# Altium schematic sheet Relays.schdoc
size 144 x 146 mm
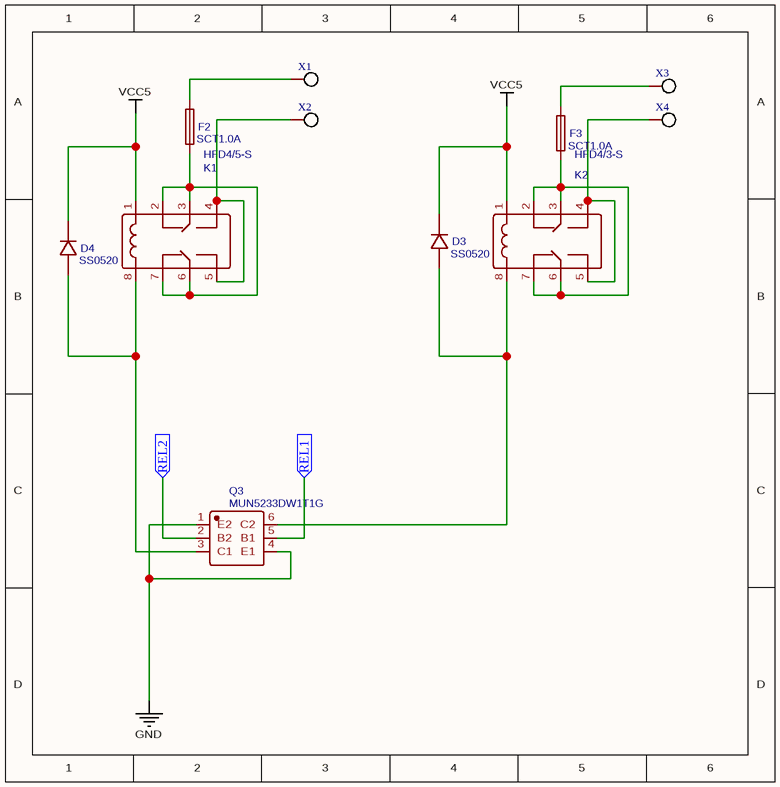
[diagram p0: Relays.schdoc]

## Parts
D3  SS0520  [SOD-123]
D4  SS0520  [SOD-123]
F2  SCT1.0A  [F-SMD-6.1X2.6]
F3  SCT1.0A  [F-SMD-6.1X2.6]
K1  HFD4/5-S  [HFD4/5-S1R]
K2  HFD4/3-S  [HFD4/5-S1R]
Q3  MUN5233DW1T1G  [SOT-363]
X1  Pad  [PAD-2.54]  (value not drawn)
X2  Pad  [PAD-2.54]  (value not drawn)
X3  Pad  [PAD-2.54]  (value not drawn)
X4  Pad  [PAD-2.54]  (value not drawn)

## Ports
REL1 (in), REL2 (in)

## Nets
GND: Q3.1(E2) Q3.4(E1)
VCC5: D3.2(K) D4.2(K) K1.1 K2.1
REL1: Q3.5(B1) ; port REL1
REL2: Q3.2(B2) ; port REL2
NetD3_1: D3.1(A) K2.8 Q3.6(C2)
NetD4_1: D4.1(A) K1.8 Q3.3(C1)
NetF2_1: F2.1 K1.2 K1.3 K1.6 K1.7
NetF2_2: F2.2 X1.1
NetF3_1: F3.1 K2.2 K2.3 K2.6 K2.7
NetF3_2: F3.2 X3.1
NetK1_4: K1.4 K1.5 X2.1
NetK2_4: K2.4 K2.5 X4.1

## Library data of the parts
D3 D4 = SS0520: BOM_Manufacturer: PANJIT International; BOM_Manufacturer Part: SS0520-R1-00001
F2 F3 = SCT1.0A: BOM_Manufacturer: TLC Electronic; Contributor: LCSC
K1 = HFD4/5-S: BOM_Manufacturer: HF; Contributor: LCSC
K2 = HFD4/3-S: BOM_Manufacturer: HF; BOM_Manufacturer Part: HFD4/5-S; Contributor: LCSC
Q3 = MUN5233DW1T1G: BOM_Manufacturer: ON; Contributor: LCSC; SMT Type: Extend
